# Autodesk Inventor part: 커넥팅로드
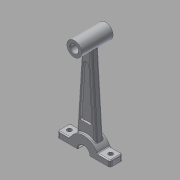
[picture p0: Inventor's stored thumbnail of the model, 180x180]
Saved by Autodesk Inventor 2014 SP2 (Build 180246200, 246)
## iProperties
Created: 2016-11
Part Number: 커넥팅로드
Material: 알루미늄 6061
Document SubType Name: Modeling
Designer: mduedu
Density: 2.71 g/cm^3
Mass: 44.549 g
Surface Area: 86.7069 cm^2
Volume: 16.4387 cm^3
Appearance: 알루미늄 - 평지
Author: mduedu
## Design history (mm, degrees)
sketch "스케치1" dims "d0" = 30, "d3" = 15
  geometry: L1 (0, 0)-(0, 96); L2 (-5, 90.41)-(-10, 11.18); L3 (5, 90.41)-(10, 11.18); C1 r 6 at (0, 0); C2 r 4 at (0, 96); 3 further points
  constraints: 6 end point, 4 coincident, 2 centre point, 2 symmetric about line, 1 vertical, 6 other
  dimensions: "d1" = 12 diameter of C1; "d2" = 8 diameter of C2; "d4" = 96 distance of L1.start L1.end; "d6" = 10 distance from line of L1 L2.end; "d7" = 5 distance from line of L1 L2.start
extrude "돌출1" new body sketch "스케치1" stored distance "d8" = 13; taper "d9" = 0 deg
extrude "돌출2" join sketch "스케치1" stored distance "d10" = 32; taper "d11" = 0 deg
sketch "스케치2"
  geometry: L1 (5, 90.41)-(10, 11.18) reference; L2 (-5, 90.41)-(-10, 11.18) reference; A1 r 7.5 centre (0, 96) between (5, 90.41) and (-5, 90.41) reference; A2 r 15 centre (0, 0) between (10, 11.18) and (-10, 11.18) reference
extrude "돌출3" join sketch "스케치2" stored distance "d12" = 8; taper "d13" = 0 deg
sketch "스케치3"
  geometry: L1 (-2.732, 78.715)-(-6.171, 24.226); L2 (2.732, 78.715)-(6.171, 24.226); L3 (0, 78.5)-(0, 25); A1 r 17.5 centre (0, 96) between (-2.732, 78.715) and (2.732, 78.715); A2 r 25 centre (0, 0) between (6.171, 24.226) and (-6.171, 24.226); 9 further points; 2 other entities
  constraints: 6 end point, 6 point on circle, 2 centre point, 1 symmetric about line, 1 vertical alignment, 6 other
  dimensions: "d18" = 10 dimension on A1; "d19" = 10 dimension on A2; "d20" = 3 dimension on L1
extrude "돌출4" cut sketch "스케치3" distance "d21" = 2; taper "d22" = 0 deg
fillet "모깎기1" dims "d23" = 2
fillet "모깎기2" dims "d24" = 2
fillet "모깎기3" dims "d25" = 1
chamfer "모따기1" distance "d26" = 0.5; stored, may be unused: second distance "d27" = 2, angle "d28" = 45 deg
sketch "스케치4"
  geometry: L1 (-27, -6)-(-13.748, -6); L2 (27, -6)-(27, 6); L3 (27, 6)-(13.748, 6); L4 (-27, 6)-(-27, -6); L5 (-27, -6)-(27, 6); L6 (27, -6)-(-27, 6); L7 (-13.748, 6)-(-27, 6); L8 (13.748, 6)-(-13.748, 6); L9 (13.748, -6)-(27, -6); L10 (-13.748, -6)-(13.748, -6); A1 r 15 centre (0, 0) between (-13.748, 6) and (13.748, 6) reference; 1 further point
  constraints: 20 end point, 10 parallel, 4 point on circle, 3 horizontal, 3 perpendicular, 2 midpoint
  dimensions: "d29" = 54 distance of L1.start L2.start; "d31" = 12 distance of L2.start L2.end
extrude "돌출5" join sketch "스케치4" stored distance "d32" = 0; taper "d33" = 0 deg
fillet "모깎기4" dims "d34" = 2
fillet "모깎기5" dims "d35" = 1
fillet "모깎기6" dims "d36" = 1
sketch "스케치5"
  geometry: L1 (1, 0)-(1, 9) reference; L2 (-18.5, 20.5)-(-33.5, 20.5) reference; L3 (-33.5, -11.5)-(-18.5, -11.5) reference; L4 (-26, 20.5)-(-26, -11.5); 3 further points
  constraints: 2 end point, 2 midpoint, 1 horizontal alignment, 1 symmetric about line
  dimensions: "d37" = 6 distance from line of point (-5, 4.5) L1
feature "분할1"
sketch "스케치7"
  geometry: 2 further points
  constraints: 2 other
hole "구멍2" sketch "스케치7" at (-47, 4.5), (-5, 4.5) diameter "d45" = 4.5; stored, may be unused: countersink angle "d49" = 90 deg, drill point angle "d51" = 0 deg; dims "d46" = 6, "d47" = 4, "d48" = 2, "d50" = 8
node "솔리드1"
mirror "대칭1"
other parameters: "d16" = 4, "d17" = 4
